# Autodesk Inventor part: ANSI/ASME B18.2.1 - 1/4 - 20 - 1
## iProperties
Author: Elise Moss
Created: 2002-03
Part Number: ANSI/ASME B18.2.1 - 1/4 - 20 - 1
Catalog Web Link: file:///C:/Program%20Files/Autodesk/Inventor%205/Content/Ansi/index.htm?doNavigateId=10493E0C-1235-495B-BF36-1591C2C4B5C1|0D631C78D7FD11D4BA8200C04F798F98|true
Description: Hex Bolt - UNC (Regular Thread - Inch)
Document SubType Name: Standard Catalog Part
Standard: ANSI/ASME B18.2.1 - 1/4 - 20 - 1
Designer: Elise Moss
CLASSIFICATION: 31161513 un/spsc
MANUFACTURER: ANSI Standard System
Control State: 0
Master: False
Checked Out: False
PropertySet Name: Design Tracking Control
Shininess: 64.0
Angle Display Precision: 2
Document Length Units: 11269
Document Angle Units: 11283
Document Time Units: 11279
Document Mass Units: 11290
Document Length Units Precision: 3
Document Angle Units Precision: 2
Compacted: False
PropertySet Name: _Private Model Information
Density: 0.0
Volumn: 0.0
Area: 0.0
PropertySet Name: Model Information
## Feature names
1. Base1
